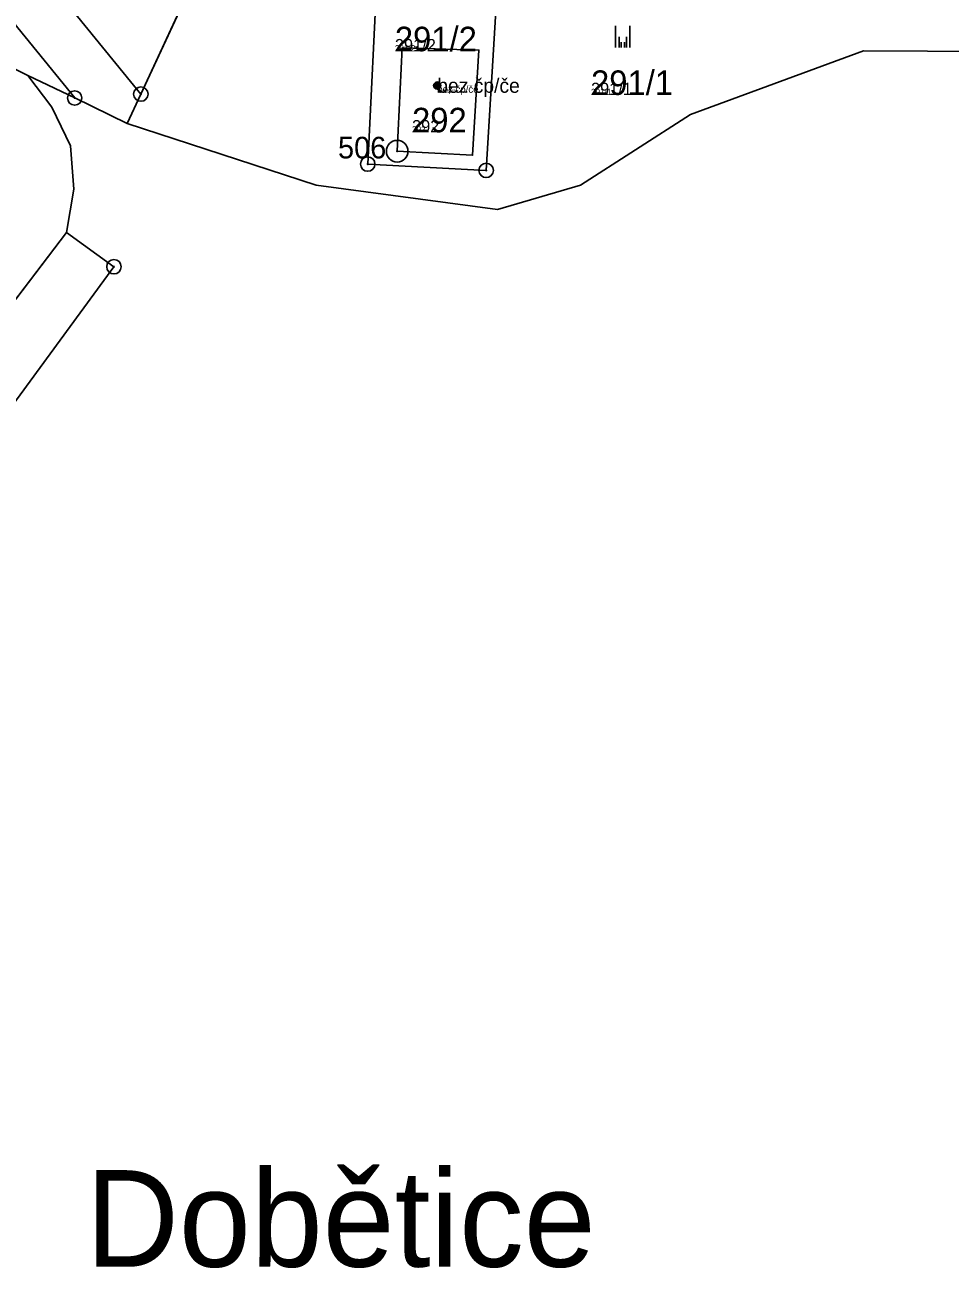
# Model space of a CAD drawing. Extents: x -759873 to -758487, y -975024 to -973516.
# Drawn here: x -759064.4 to -759000.3, y -974448.4 to -974362.2 of the extents above; entities that cross this region are included whole.
import ezdxf

# ---------------------------------------------------------------- set-up
doc = ezdxf.new("R2010")
doc.units = 0
for name, color, linetype in [('KAT_02_hranice parcel', 7, 'Continuous'), ('KAT_03_1000_st čísla parcelní', 7, 'Continuous'), ('KAT_03_1000_čísla parcelní', 7, 'Continuous'), ('KAT_03_1000_čísla popisná', 7, 'Continuous'), ('KAT_03_250_st čísla parcelní', 7, 'Continuous'), ('KAT_03_250_čísla parcelní', 7, 'Continuous'), ('KAT_03_250_čísla popisná', 7, 'Continuous'), ('KAT_03_500_st čísla parcelní', 7, 'Continuous'), ('KAT_03_500_čísla parcelní', 7, 'Continuous'), ('KAT_03_500_čísla popisná', 7, 'Continuous'), ('KAT_05_1000_značky kultur', 7, 'Continuous'), ('KAT_05_250_značky kultur', 7, 'Continuous'), ('KAT_05_500_značky kultur', 7, 'Continuous'), ('KAT_07_1000_značky budov', 7, 'Continuous'), ('KAT_07_250_značky budov', 7, 'Continuous'), ('KAT_07_500_značky budov', 7, 'Continuous'), ('KAT_11_značky bodu BP', 7, 'Continuous'), ('KAT_13_popis', 7, 'Continuous'), ('KAT_14_plocha_budovy', 7, 'Continuous'), ('KAT_14_plocha_pozemek', 7, 'Continuous')]:
    doc.layers.add(name, color=color, linetype=linetype)

msp = doc.modelspace()

# ---------------------------------------------------------------- linework, layer by layer
at = {"layer": 'KAT_02_hranice parcel'}
for p, q in [((-759051.14, -974355.72), (-759056.37, -974366.99)), ((-759060.96, -974367.26), (-759064.2, -974365.69)), ((-759057.32, -974369.03), (-759060.96, -974367.26)), ((-759056.37, -974366.99), (-759057.32, -974369.03)), ((-759069.78, -974387.41), (-759061.52, -974376.58))]:
    msp.add_line(p, q, dxfattribs=at)
for points in [[(-759056.37, -974366.99), (-759070.29, -974349.93), (-759074.99, -974338.96)], [(-759074.68, -974375.99), (-759084.95, -974368.78), (-759072.61, -974352.91), (-759060.96, -974367.26)], [(-759031.63, -974358.94), (-759032.43, -974372.28), (-759040.64, -974371.84), (-759039.97, -974358.1)], [(-758867.55, -974396.24), (-758911.81, -974379.4), (-758952.35, -974369.35), (-758971.41, -974365.53), (-758992.93, -974364.06), (-759006.26, -974363.99), (-759018.27, -974368.4), (-759025.9, -974373.3), (-759031.64, -974374.99), (-759044.21, -974373.31), (-759057.32, -974369.03)], [(-759038.25, -974363.78), (-759038.6, -974370.95), (-759033.37, -974371.23), (-759032.93, -974363.94), (-759038.25, -974363.78)], [(-759064.2, -974365.69), (-759066.62, -974364.52), (-759074.68, -974375.99)], [(-759064.2, -974365.69), (-759062.54, -974367.9), (-759061.25, -974370.57), (-759061.03, -974373.59), (-759061.52, -974376.58)], [(-759061.52, -974376.58), (-759058.24, -974378.96), (-759093.33, -974426.86), (-759081.81, -974435.94), (-759082.1, -974437)]]:
    msp.add_lwpolyline(points, dxfattribs=at)
at = {"layer": 'KAT_03_1000_čísla popisná'}
msp.add_circle((-759035.82, -974366.4), 0.25, dxfattribs=at)
at = {"layer": 'KAT_03_250_čísla popisná'}
msp.add_circle((-759035.82, -974366.4), 0.0625, dxfattribs=at)
at = {"layer": 'KAT_03_500_čísla popisná'}
msp.add_circle((-759035.82, -974366.4), 0.125, dxfattribs=at)
at = {"layer": 'KAT_05_1000_značky kultur'}
for p, q in [((-759023.461, -974363.76), (-759023.461, -974362.26)), ((-759022.46, -974363.76), (-759022.46, -974362.26))]:
    msp.add_line(p, q, dxfattribs=at)
at = {"layer": 'KAT_05_250_značky kultur'}
for p, q in [((-759023.078, -974363.76), (-759023.078, -974363.385)), ((-759022.828, -974363.76), (-759022.828, -974363.385))]:
    msp.add_line(p, q, dxfattribs=at)
at = {"layer": 'KAT_05_500_značky kultur'}
for p, q in [((-759023.206, -974363.76), (-759023.206, -974363.01)), ((-759022.705, -974363.76), (-759022.705, -974363.01))]:
    msp.add_line(p, q, dxfattribs=at)
at = {"layer": 'KAT_07_1000_značky budov'}
msp.add_circle((-759035.827, -974366.399), 0.175, dxfattribs=at)
at = {"layer": 'KAT_07_250_značky budov'}
msp.add_circle((-759035.822, -974366.4), 0.0437, dxfattribs=at)
at = {"layer": 'KAT_07_500_značky budov'}
msp.add_circle((-759035.823, -974366.4), 0.0875, dxfattribs=at)
at = {"layer": 'KAT_11_značky bodu BP'}
for centre, radius in [((-759056.37, -974366.99), 0.5), ((-759060.96, -974367.26), 0.5), ((-759060.96, -974367.26), 0.0303), ((-759056.37, -974366.99), 0.0303), ((-759038.6, -974370.95), 0.75), ((-759038.6, -974370.95), 0.03), ((-759040.64, -974371.84), 0.5), ((-759040.64, -974371.84), 0.0303), ((-759032.43, -974372.28), 0.5), ((-759032.43, -974372.28), 0.0303), ((-759058.24, -974378.96), 0.5), ((-759058.24, -974378.96), 0.0303)]:
    msp.add_circle(centre, radius, dxfattribs=at)
at = {"layer": 'KAT_14_plocha_budovy'}
msp.add_lwpolyline([(-759038.6, -974370.95), (-759033.37, -974371.23), (-759032.93, -974363.94), (-759038.25, -974363.78)], close=True, dxfattribs=at)
at = {"layer": 'KAT_14_plocha_pozemek'}
for points in [[(-759076.68, -974378.83), (-759074.68, -974375.99), (-759084.95, -974368.78), (-759072.61, -974352.91), (-759060.96, -974367.26), (-759057.32, -974369.03), (-759056.37, -974366.99), (-759070.29, -974349.93), (-759074.99, -974338.96), (-759079.48, -974333.82), (-759079.47, -974336.54), (-759079.45, -974344.13), (-759075.8, -974349.7), (-759090.51, -974368.61), (-759087.6, -974371.21)], [(-759074.99, -974338.96), (-759070.29, -974349.93), (-759056.37, -974366.99), (-759051.14, -974355.72), (-759060.98, -974351.22), (-759070.5, -974344.1)], [(-759060.96, -974367.26), (-759072.61, -974352.91), (-759084.95, -974368.78), (-759074.68, -974375.99), (-759066.62, -974364.52), (-759064.2, -974365.69)], [(-759040.64, -974371.84), (-759039.97, -974358.1), (-759051.14, -974355.72), (-759056.37, -974366.99), (-759057.32, -974369.03), (-759044.21, -974373.31), (-759031.64, -974374.99), (-759025.9, -974373.3), (-759018.27, -974368.4), (-759006.26, -974363.99), (-758992.93, -974364.06), (-758971.41, -974365.53), (-758952.35, -974369.35), (-758911.81, -974379.4), (-758867.55, -974396.24), (-758881.44, -974386.63), (-758930.04, -974363.17), (-758978.01, -974362.06), (-759031.63, -974358.94), (-759032.43, -974372.28)], [(-759039.97, -974358.1), (-759040.64, -974371.84), (-759032.43, -974372.28), (-759031.63, -974358.94), (-759037.67, -974358.59)], [(-759038.25, -974363.78), (-759032.93, -974363.94), (-759033.37, -974371.23), (-759038.6, -974370.95)], [(-759038.25, -974363.78), (-759038.6, -974370.95), (-759033.37, -974371.23), (-759032.93, -974363.94)], [(-759077.6, -974380.14), (-759077.77, -974380.4), (-759069.78, -974387.41), (-759061.52, -974376.58), (-759061.03, -974373.59), (-759061.25, -974370.57), (-759062.54, -974367.9), (-759064.2, -974365.69), (-759066.62, -974364.52), (-759074.68, -974375.99), (-759076.68, -974378.83)], [(-759089.09, -974397.95), (-759084.64, -974401.73), (-759085.22, -974407.61), (-759090.74, -974414.83), (-759093.21, -974416.46), (-759096.02, -974416.88), (-759099.33, -974416.17), (-759100.34, -974415.37), (-759101.95, -974417.87), (-759103.4, -974420.2), (-759101.64, -974421.6), (-759097.66, -974424.74), (-759082.1, -974437), (-759081.81, -974435.94), (-759093.33, -974426.86), (-759058.24, -974378.96), (-759061.52, -974376.58), (-759069.78, -974387.41), (-759076.55, -974396.16), (-759083.9, -974397.03), (-759086.82, -974394.42)]]:
    msp.add_lwpolyline(points, close=True, dxfattribs=at)
msp.add_lwpolyline([(-758992.93, -974364.06), (-759006.26, -974363.99), (-759018.27, -974368.4), (-759025.9, -974373.3), (-759031.64, -974374.99), (-759044.21, -974373.31), (-759057.32, -974369.03), (-759060.96, -974367.26), (-759064.2, -974365.69), (-759062.54, -974367.9), (-759061.25, -974370.57), (-759061.03, -974373.59), (-759061.52, -974376.58), (-759058.24, -974378.96), (-759093.33, -974426.86)], dxfattribs=at)

# ---------------------------------------------------------------- texts
at = {"layer": 'KAT_03_1000_st čísla parcelní'}
msp.add_text('292', height=1.7, dxfattribs=at).set_placement((-759037.57, -974369.64))
at = {"layer": 'KAT_03_1000_čísla parcelní'}
for s, p in [('291/2', (-759038.76, -974364.02)), ('291/1', (-759025.16, -974367.049))]:
    msp.add_text(s, height=1.7, dxfattribs=at).set_placement(p)
at = {"layer": 'KAT_03_1000_čísla popisná'}
msp.add_text('bez čp/če', height=1, dxfattribs=at).set_placement((-759035.82, -974366.9))
at = {"layer": 'KAT_03_250_st čísla parcelní'}
msp.add_text('292', height=0.425, dxfattribs=at).set_placement((-759037.57, -974369.64))
at = {"layer": 'KAT_03_250_čísla parcelní'}
for s, p in [('291/2', (-759038.76, -974364.02)), ('291/1', (-759025.16, -974367.049))]:
    msp.add_text(s, height=0.425, dxfattribs=at).set_placement(p)
at = {"layer": 'KAT_03_250_čísla popisná'}
msp.add_text('bez čp/če', height=0.25, dxfattribs=at).set_placement((-759035.82, -974366.9))
at = {"layer": 'KAT_03_500_st čísla parcelní'}
msp.add_text('292', height=0.85, dxfattribs=at).set_placement((-759037.57, -974369.64))
at = {"layer": 'KAT_03_500_čísla parcelní'}
for s, p in [('291/2', (-759038.76, -974364.02)), ('291/1', (-759025.16, -974367.049))]:
    msp.add_text(s, height=0.85, dxfattribs=at).set_placement(p)
at = {"layer": 'KAT_03_500_čísla popisná'}
msp.add_text('bez čp/če', height=0.5, dxfattribs=at).set_placement((-759035.82, -974366.9))
at = {"layer": 'KAT_11_značky bodu BP'}
msp.add_text('506', height=1.5, dxfattribs=at).set_placement((-759042.703, -974371.45))
at = {"layer": 'KAT_13_popis'}
msp.add_text('Dobětice', height=6.7, dxfattribs=at).set_placement((-759060.2, -974448.289))

doc.saveas('drawing.dxf')
